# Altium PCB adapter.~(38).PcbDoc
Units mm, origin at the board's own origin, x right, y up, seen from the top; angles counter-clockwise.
Board outline 43.1 x 112 mm, 4 copper layers (Top Layer, Layer 1, Layer 2, Bottom Layer), stack 1.57 mm thick; 4 components, 39 nets, 158 pads, 97 vias.
Unrouted connection lines stored in the file: 79.
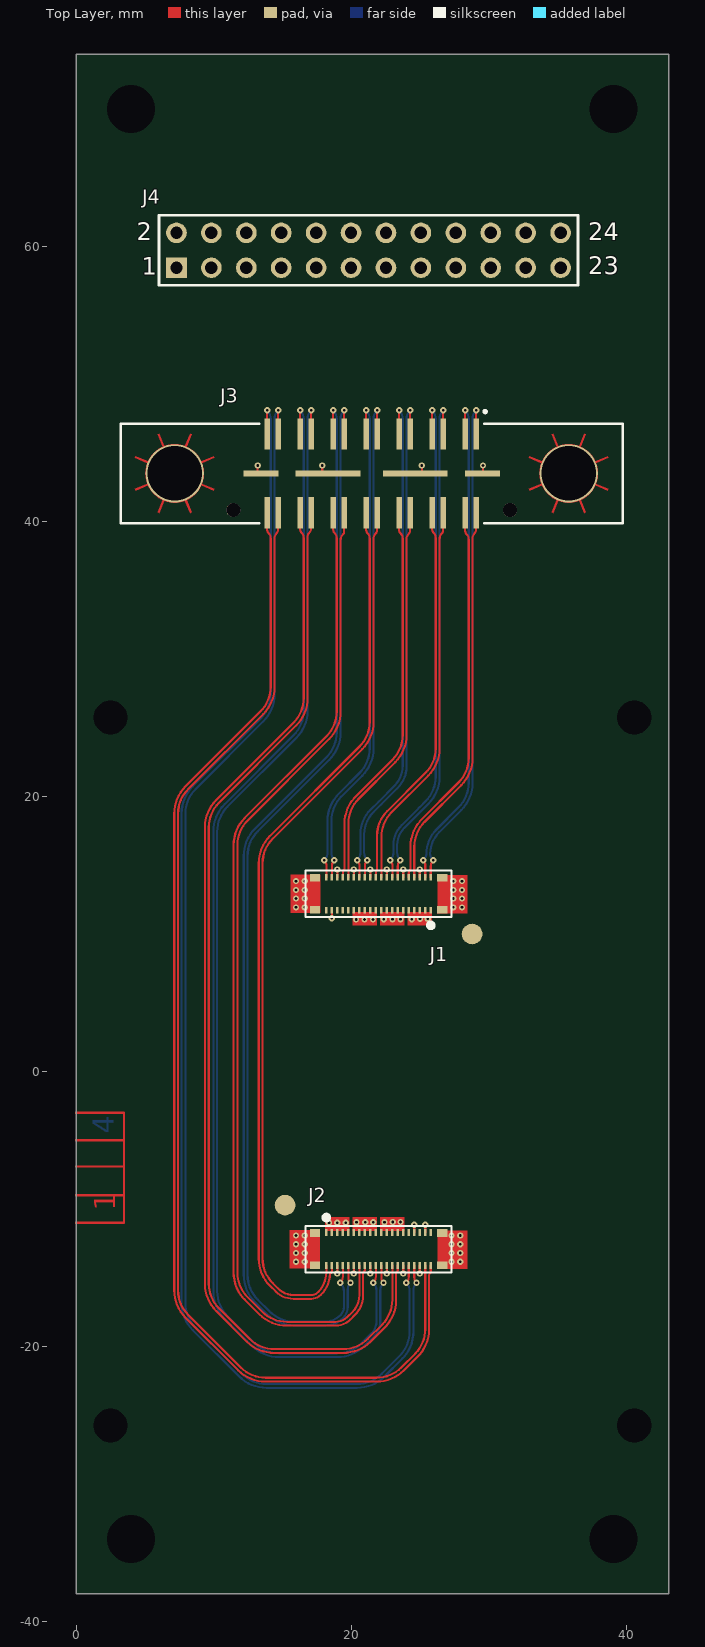
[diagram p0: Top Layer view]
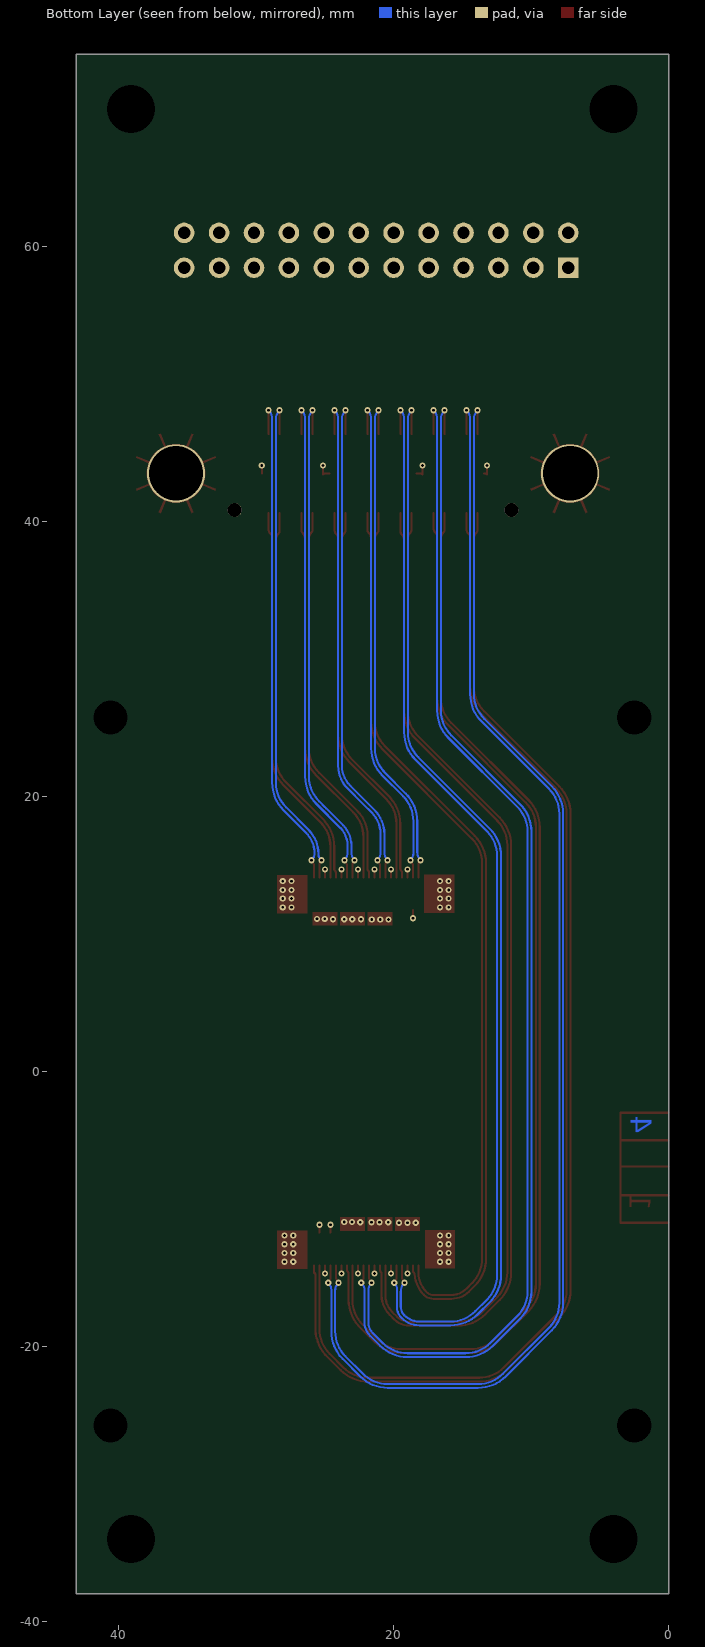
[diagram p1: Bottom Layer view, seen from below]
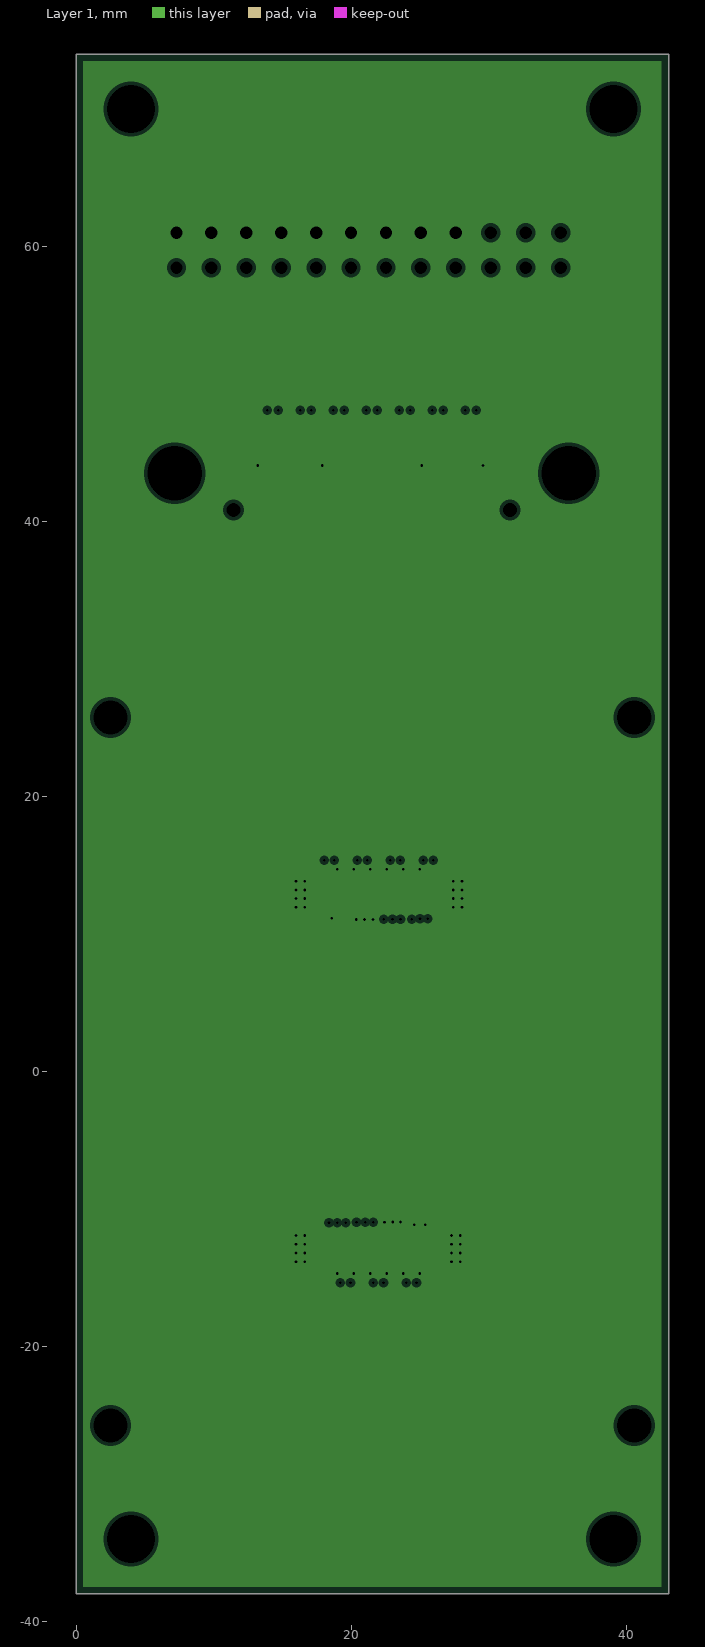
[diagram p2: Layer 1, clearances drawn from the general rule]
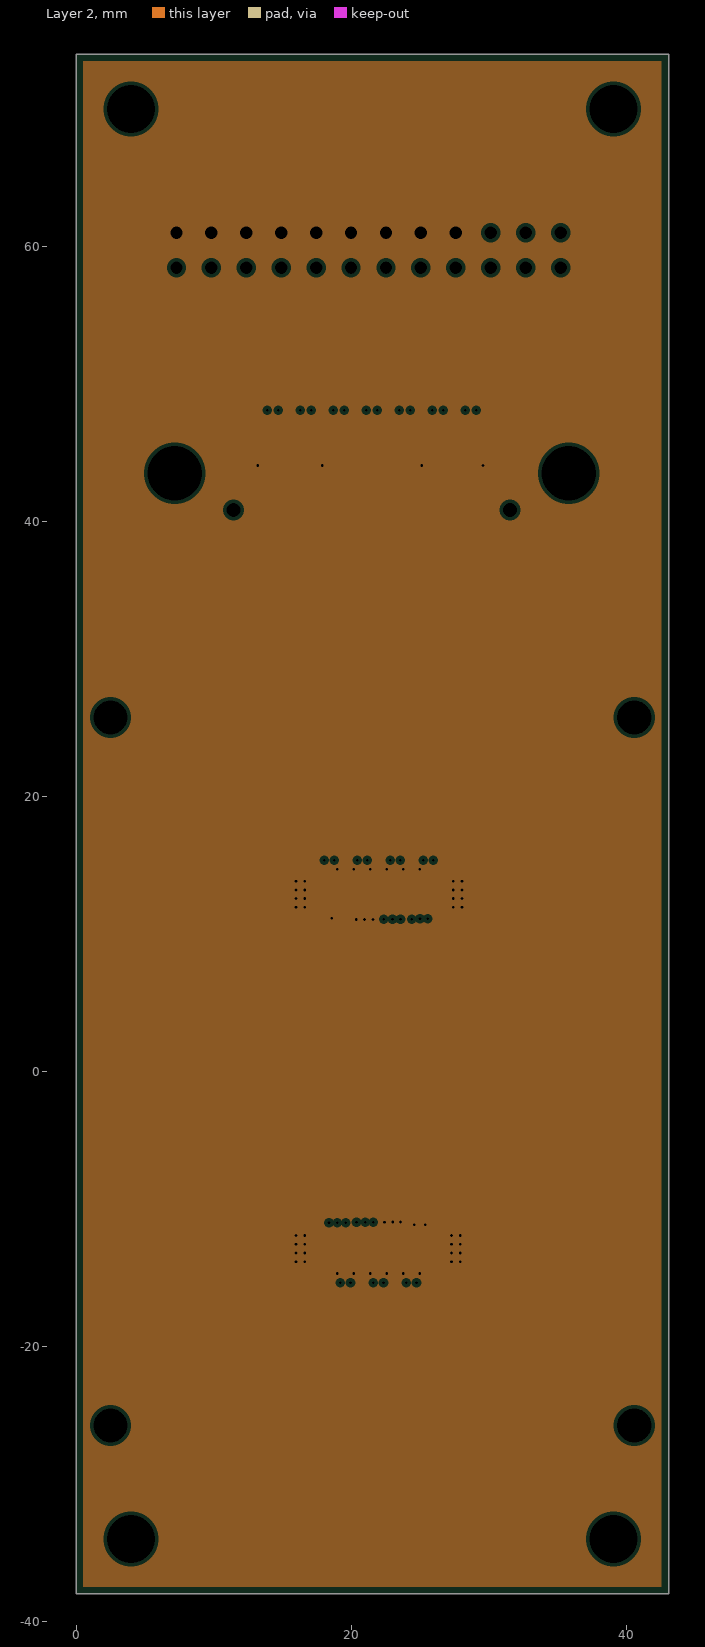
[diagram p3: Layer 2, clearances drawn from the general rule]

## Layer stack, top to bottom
Top Solder: solder mask 0.0102, Solder Resist, Dk 3.5
Top Layer: signal copper 0.035
Dielectric 1: prepreg 0.2, 7628, Dk 4.6
Layer 1: plane copper 0.0175, net GND
Dielectric 2: core 1.065, FR-4, Dk 4.5
Layer 2: plane copper 0.0175, net GND
Dielectric 3: prepreg 0.2, 7628, Dk 4.6
Bottom Layer: signal copper 0.035
Bottom Solder: solder mask 0.0102, Solder Resist, Dk 3.5

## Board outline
0,-38 43.1,-38 43.1,74 0,74

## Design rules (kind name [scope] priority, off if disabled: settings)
Clearance [All] p1: gap=0.2 ignorepadtopadclearanceinfootprint=FALSE except(0: Arc-Hole Track-Hole SMDPad-Hole THPad-Hole Via-Hole Fill-Hole Poly-Hole Region-Hole Text-Hole; 0.089: Arc-Via Track-Via SMDPad-Via Via-Via; 0.127: Arc-Arc Arc-Track Arc-THPad Track-Track Track-THPad THPad-Via; 0.15: Arc-SMDPad Track-SMDPad SMDPad-SMDPad; 0.254: Arc-Text Track-Text SMDPad-THPad SMDPad-Text THPad-THPad THPad-Text Via-Text Fill-Text Poly-Text Region-Text Text-Text)
DiffPairsRouting [All] p1: maxlimit=0.254 minlimit=0.127 mostfreqgap=0.127 toplayer_minwidth=0.152 toplayer_maxwidth=0.152 toplayer_prefwidth=0.152 bottomlayer_minwidth=0.152 bottomlayer_maxwidth=0.152 bottomlayer_prefwidth=0.152 maxuncoupledlength=12.7
HoleSize [All] p1: absolutevalues=TRUE maxlimit=5.08 minlimit=0.025 maxpercent=80.000 minpercent=20.000
MinimumSolderMaskSliver [All] p1: minsoldermaskwidth=0.12
PlaneClearance [All] p1: clearance=0.254
PlaneConnect [All] p1: pad.planeconnectstyle=Relief pad.reliefexpansion=0.508 pad.reliefentries=4 pad.reliefconductorwidth=0.254 pad.reliefairgap=0.254 via.planeconnectstyle=Direct via.reliefexpansion=0.508 via.reliefentries=4 via.reliefconductorwidth=0.254 via.reliefairgap=0.254
PolygonConnect [All] p1: connectstyle=Relief reliefconductorwidth=0.254 reliefentries=4 polygonreliefangle="90 Angle" airgapwidth=0.254
RoomDefinition emu_adapter [InComponentClass('emu_adapter')] p1: confinementstyle=ConfineIn formatcopy=TRUE lockcomponents=FALSE outline -2.8,-38 45.6,-38 45.6,74 -2.8,74
RoutingCorners [All] p1: cornerstyle=Round minsetback=2.54 maxsetback=2.54
RoutingVias [All] p1: holewidth=0.2 width=0.45 viastyle="Through Hole" minholewidth=0.2 minwidth=0.45 maxholewidth=0.3 maxwidth=0.55
SMDEntry [(InDifferentialPairClass('All Differential Pairs'))] p1: side=FALSE corner=FALSE anyangle=FALSE
SilkToSolderMaskClearance [IsPad] p1: minsilkscreentomaskgap=0.15 clearancetoexposedcopper=TRUE
SolderMaskExpansion [All] p1: expansion=0.038 istentingtop=FALSE
Width [All] p1: maxlimit=0.254 minlimit=0.152 preferedwidth=0.152 minimp=50.000000 maximp=50.000000 favimp=50.000000
23 further rules are at their usual default settings.

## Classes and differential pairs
differential pair T_EDIN3: +T_EDIN3_P -T_EDIN3_N
differential pair T_EDIN2: +T_EDIN2_P -T_EDIN2_N
differential pair T_EDIN1: +T_EDIN1_P -T_EDIN1_N
differential pair T_EDIN0: +T_EDIN0_P -T_EDIN0_N
differential pair EDOUT1: +EDOUT1_P -EDOUT1_N
differential pair EDOUT0: +EDOUT0_P -EDOUT0_N
differential pair EDIN3: +EDIN3_P -EDIN3_N
differential pair EDIN2: +EDIN2_P -EDIN2_N
differential pair EDIN1: +EDIN1_P -EDIN1_N
differential pair EDIN0: +EDIN0_P -EDIN0_N
differential pair ECLK3: +ECLK3_P -ECLK3_N
differential pair ECLK2: +ECLK2_P -ECLK2_N
differential pair ECLK1: +ECLK1_P -ECLK1_N
differential pair ECLK0: +ECLK0_P -ECLK0_N

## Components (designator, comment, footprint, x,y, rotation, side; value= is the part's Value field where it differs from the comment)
J1 "WP7B-S040VA1" WP7B-40R 25.8,11.725 r0 top locked
J2 "WP7B-S040VA1" WP7B-40R 18.2,-11.725 r180 top locked
J3 "QSE-014-01-X-D-DP-A-RT1" SAMTEC_QSE-014-01-X-D-DP-A-RT1 21.5,43.5 r180 top locked
J4 "Header 12X2" HDR2X12 7.3,58.46 r0 top

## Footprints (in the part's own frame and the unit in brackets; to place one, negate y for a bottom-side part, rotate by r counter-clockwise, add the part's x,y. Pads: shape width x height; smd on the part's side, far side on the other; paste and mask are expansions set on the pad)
HDR2X12 [mm] "Connector; Header; 12x2 Position"
  rect 1.5x1.5 hole 0.9: 1(0,0)
  round 1.5 hole 0.9: 2(0,2.54) 3(2.54,0) 4(2.54,2.54) 5(5.08,0) 6(5.08,2.54) 7(7.62,0) 8(7.62,2.54) 9(10.16,0) 10(10.16,2.54) 11(12.7,0) 12(12.7,2.54) 13(15.24,0) 14(15.24,2.54) 15(17.78,0) 16(17.78,2.54) 17(20.32,0) 18(20.32,2.54) 19(22.86,0) 20(22.86,2.54) 21(25.4,0) 22(25.4,2.54) 23(27.94,0) 24(27.94,2.54)
  silkscreen extent -1.27,-1.27 29.21,3.81
SAMTEC_QSE-014-01-X-D-DP-A-RT1 [mm]
  rect 0.41x2.27 smd: 01(-7.6,-2.865) 02(-7.6,2.865) 03(-6.8,-2.865) 04(-6.8,2.865) 05(-5.2,-2.865) 06(-5.2,2.865) 07(-4.4,-2.865) 08(-4.4,2.865) 09(-2.8,-2.865) 10(-2.8,2.865) 11(-2,-2.865) 12(-2,2.865) 13(-0.4,-2.865) 14(-0.4,2.865) 15(0.4,-2.865) 16(0.4,2.865) 17(2,-2.865) 18(2,2.865) 19(2.8,-2.865) 20(2.8,2.865) 21(4.4,-2.865) 22(4.4,2.865) 23(5.2,-2.865) 24(5.2,2.865) 25(6.8,-2.865) 26(6.8,2.865) 27(7.6,-2.865) 28(7.6,2.865)
  round 4.24 hole 3.96: 29(-14.33,0) 30(14.33,0)
  rect 2.54x0.43 smd: GND1(-8.065,0) GND4(8.065,0)
  rect 4.7x0.43 smd: GND2(-3.175,0) GND3(3.175,0)
  round 1.02 hole 1.02 unplated: ""(-10.065,2.67) ""(10.065,2.67)
  Top Layer region: 265 vertices and 0 holes, not listed, extent -17.219,-2.889 -11.442,2.889
  Top Layer region: 265 vertices and 0 holes, not listed, extent 11.442,-2.889 17.219,2.889
  silkscreen extent -18.26,-4.6 18.26,3.62
WP7B-40R [mm]
  rect 0.2x0.5 smd: 1(0,0) 2(-0.4,0) 3(-0.8,0) 4(-1.2,0) 5(-1.6,0) 6(-2,0) 7(-2.4,0) 8(-2.8,0) 9(-3.2,0) 10(-3.6,0) 11(-4,0) 12(-4.4,0) 13(-4.8,0) 14(-5.2,0) 15(-5.6,0) 16(-6,0) 17(-6.4,0) 18(-6.8,0) 19(-7.2,0) 20(-7.6,0) 21(-7.6,2.4) 22(-7.2,2.4) 23(-6.8,2.4) 24(-6.4,2.4) 25(-6,2.4) 26(-5.6,2.4) 27(-5.2,2.4) 28(-4.8,2.4) 29(-4.4,2.4) 30(-4,2.4) 31(-3.6,2.4) 32(-3.2,2.4) 33(-2.8,2.4) 34(-2.4,2.4) 35(-2,2.4) 36(-1.6,2.4) 37(-1.2,2.4) 38(-0.8,2.4) 39(-0.4,2.4) 40(0,2.4)
  rect 0.75x0.55 smd: 41(0.825,0.025) 42(-8.425,0.025) 43(-8.425,2.375) 44(0.825,2.375)
  silkscreen extent -9.1,-1.2 1.5,2.9, body extent -9.1,-0.05 1.5,2.45, height 0.5

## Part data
J1 J2: library part WP7B-40R, "receptacle"
J3: "28 Position Connector Differential Pair Array, Female Surface Mount Gold", Package=None
J4: "Header, 12-Pin, Dual row"

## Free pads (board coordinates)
  round 1 hole 2.5 unplated: 1(2.5,-25.75) 1(2.5,25.75) 1(40.6,-25.75) 1(40.6,25.75)
  round 1.5 smd paste-2: 1(28.8,10) 4(15.2,-9.725)
  round 1.5 hole 3.5: 5(39.1,70) 6(4,70) 7(39.1,-34) 8(4,-34)

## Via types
v1: diameter 0.45, hole 0.2, Top Layer to Bottom Layer, 97 vias

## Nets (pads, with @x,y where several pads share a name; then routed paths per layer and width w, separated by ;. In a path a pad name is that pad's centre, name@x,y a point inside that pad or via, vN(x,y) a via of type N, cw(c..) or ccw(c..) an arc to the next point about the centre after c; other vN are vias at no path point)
1V0A: J1.20 J4.23
1V2_mon0: J1.17 J4.19
1V2_mon1: J1.18 J4.21
1V2A: J1.1 J1.2 J1.3 J1.4 J1.5 J4.1 J4.3
  other v1: 24.409,11.074 25.019,11.1 25.578,11.1
1V2B: J1.6 J1.7 J1.8 J1.9 J1.10 J4.5 J4.7
  other v1: 22.377,11.074 23.012,11.074 23.597,11.074
1V2C: J2.1 J2.2 J2.3 J2.4 J2.5 J4.9 J4.11 J4.13
  other v1: 18.39,-10.998 18.999,-10.998 19.609,-10.998
1V2D: J2.6 J2.7 J2.8 J2.9 J2.10 J4.15 J4.17
  other v1: 20.396,-10.973 21.031,-10.973 21.615,-10.973
ECLK0_N: J1.39 J3.03 | length 37
  Top Layer w0.152: v1(25.247,15.367) cw(c24.878,14.998) 25.4,14.998 J1.39 ; J3.03 v1(28.3,48.099)
  Bottom Layer w0.152: v1(25.247,15.367) 25.315,15.435 ccw(c24.926,15.824) 25.476,15.824 ; 25.476,15.825 cw(c27.989,15.825) 26.212,17.601 27.816,19.206 ccw(c26.02,21.002) 28.56,21.002 28.56,47.471 ccw(c27.672,47.471) v1(28.3,48.099)
ECLK0_P: J1.40 J3.01 | length 37
  Top Layer w0.152: J1.40 25.8,14.924 cw(c26.427,14.924) v1(25.984,15.367) ; v1(29.1,48.099) J3.01 J3.01
  Bottom Layer w0.152: v1(25.984,15.367) 25.918,15.433 cw(c26.309,15.824) 25.756,15.824 cw(c27.99,15.824) 26.41,17.404 28.015,19.009 ccw(c26.023,21.001) 28.84,21.001 ; 28.84,21.001 28.84,47.471 cw(c29.728,47.471) v1(29.1,48.099)
ECLK1_N: J1.28 J3.09 | length 37
  Top Layer w0.152: J1.28 21,14.924 cw(c21.627,14.924) v1(21.184,15.367) ; v1(24.299,48.1) J3.09 J3.09
  Bottom Layer w0.152: v1(21.184,15.367) cw(c21.735,15.919) 20.955,15.919 20.955,17.252 cw(c23.21,17.252) 21.615,18.847 22.2,19.431 23.36,20.592 ccw(c21.722,22.23) 24.039,22.23 24.039,47.472 cw(c24.928,47.472) v1(24.299,48.1)
ECLK1_P: J1.27 J3.11 | length 37
  Top Layer w0.152: v1(20.447,15.367) cw(c20.078,14.998) 20.6,14.998 J1.27 ; J3.11 v1(23.499,48.1)
  Bottom Layer w0.152: v1(20.447,15.367) ccw(c19.895,15.919) 20.676,15.919 20.676,17.252 cw(c23.21,17.252) 21.418,19.044 22.002,19.629 23.16,20.786 ccw(c21.712,22.234) 23.76,22.234 23.76,47.472 ccw(c22.871,47.472) v1(23.499,48.1)
ECLK2_N: J2.40 J3.14 | length 65.1
  Top Layer w0.152: J2.40 18.2,-14.61 cw(c16.159,-14.61) 17.602,-16.053 cw(c17.112,-15.562) 17.112,-16.256 15.81,-16.256 cw(c15.81,-14.695) 14.707,-15.799 14.308,-15.4 cw(c16.104,-13.604) 13.564,-13.604 13.564,15.139 cw(c16.104,15.139) 14.308,16.935 20.815,23.442 ccw(c18.823,25.434) 21.64,25.434 21.64,38.771 cw(c22.164,38.771) 21.793,39.141 ccw(c21.535,39.399) 21.9,39.399 J3.14
ECLK2_P: J2.39 J3.16 | length 66.1
  Top Layer w0.152: 17.799,-16.251 cw(c17.113,-15.565) 17.113,-16.535 15.807,-16.535 cw(c15.807,-14.702) 14.511,-15.999 14.109,-15.596 cw(c16.101,-13.605) 13.284,-13.605 13.284,15.14 cw(c16.101,15.14) 14.109,17.132 20.616,23.639 ccw(c18.82,25.435) 21.36,25.435 21.36,38.776 ccw(c20.844,38.776) 21.209,39.141 cw(c21.472,39.405) 21.1,39.405 J3.16 ; 17.801,-16.249 ccw(c16.159,-14.61) 18.204,-15.707 ccw(c16.159,-14.61) 18.477,-14.705 cw(c19.487,-15.525) 18.567,-14.605 ccw(c18.489,-14.526) 18.6,-14.526 J2.39
ECLK3_N: J2.28 J3.22 | length 79
  Top Layer w0.152: J3.22 17.099,39.511 cw(c16.648,39.511) 16.967,39.192 ccw(c17.276,38.883) 16.839,38.883 16.839,27.161 cw(c14.022,27.161) 16.014,25.169 10.396,19.551 ccw(c12.192,17.755) 9.652,17.755 9.652,-15.432 ccw(c12.192,-15.432) 10.396,-17.229 12.616,-19.449 ccw(c14.413,-17.653) 14.413,-20.193 19.42,-20.193 ccw(c19.42,-17.653) 21.216,-19.449 22.256,-18.409 ccw(c20.46,-16.613) 23,-16.613 J2.28
ECLK3_P: J2.27 J3.24 | length 79.9
  Top Layer w0.152: J3.24 16.299,39.43 ccw(c16.672,39.43) 16.408,39.167 cw(c16.043,38.802) 16.56,38.802 16.56,27.162 cw(c14.02,27.162) 15.816,25.366 10.198,19.748 ccw(c12.19,17.756) 9.373,17.756 9.373,-15.434 ccw(c12.189,-15.434) 10.198,-17.425 12.419,-19.647 ccw(c14.412,-17.655) 14.412,-20.472 19.421,-20.472 ccw(c19.421,-17.655) 21.413,-19.647 22.574,-18.486 22.574,-18.479 ccw(c20.46,-16.613) 23.279,-16.613 23.279,-14.647 cw(c23.736,-14.897) 23.368,-14.529 ccw(c23.291,-14.452) 23.4,-14.452 J2.27
EDIN0_N: J1.34 J3.05 | length 37
  Top Layer w0.152: J1.34 23.4,14.924 cw(c24.027,14.924) v1(23.584,15.367) ; v1(26.7,48.1) J3.05 J3.05
  Bottom Layer w0.152: v1(23.584,15.367) cw(c24.135,15.919) 23.355,15.919 23.355,16.459 cw(c25.129,16.459) 23.875,17.714 25.614,19.453 ccw(c23.622,21.445) 26.439,21.445 26.439,47.472 cw(c27.328,47.472) v1(26.7,48.1)
EDIN0_P: J1.33 J3.07 | length 36.8
  Top Layer w0.152: v1(22.847,15.367) cw(c22.478,14.998) 23,14.998 J1.33 ; J3.07 v1(25.9,48.1)
  Bottom Layer w0.152: v1(22.847,15.367) ccw(c22.295,15.919) 23.076,15.919 23.076,16.46 cw(c25.127,16.46) 23.677,17.911 24.912,19.146 ; 24.994,19.228 25.416,19.65 ccw(c23.62,21.446) 26.16,21.446 26.16,47.472 ccw(c25.271,47.472) v1(25.9,48.1)
EDIN1_N: J1.25 J3.10 | length 28.1
  Top Layer w0.152: J1.25 19.8,18.023 cw(c22.34,18.023) 20.544,19.819 23.215,22.49 ccw(c21.223,24.482) 24.04,24.482 24.04,38.751 cw(c24.521,38.751) 24.181,39.091 ccw(c23.892,39.379) 24.3,39.379 J3.10
EDIN1_P: J1.24 J3.12 | length 28.1
  Top Layer w0.152: J1.24 19.4,14.458 cw(c19.679,14.458) 19.482,14.656 ccw(c19.388,14.749) 19.521,14.749 19.521,18.023 cw(c22.34,18.023) 20.226,19.888 20.226,19.896 23.017,22.686 ccw(c21.221,24.483) 23.761,24.483 23.761,38.745 ccw(c23.201,38.745) 23.597,39.141 cw(c23.829,39.374) 23.5,39.374 J3.12
EDIN2_N: J2.34 J3.18 | length 72.2
  Top Layer w0.152: J3.18 19.5,39.257 cw(c19.265,39.257) 19.431,39.091 ccw(c19.894,38.628) 19.239,38.628 19.239,26.183 cw(c16.422,26.183) 18.414,24.191 12.479,18.256 ccw(c14.275,16.46) 11.735,16.46 11.735,-14.62 ccw(c14.275,-14.62) 12.479,-16.416 13.531,-17.468 ccw(c15.327,-15.672) 15.327,-18.212 18.872,-18.212 ccw(c18.872,-16.985) 19.739,-17.853 20.091,-17.501 ccw(c18.864,-16.273) 20.6,-16.273 J2.34
EDIN2_P: J2.33 J3.20 | length 73.1
  Top Layer w0.152: J3.20 18.7,39.435 ccw(c19.115,39.435) 18.821,39.141 cw(c18.487,38.807) 18.96,38.807 18.96,26.184 cw(c16.42,26.184) 18.216,24.388 12.281,18.453 ccw(c14.273,16.461) 11.455,16.461 11.455,-14.621 ccw(c14.272,-14.621) 12.28,-16.612 13.334,-17.666 ccw(c15.326,-15.674) 15.326,-18.491 18.873,-18.491 ccw(c18.873,-16.988) 19.936,-18.051 20.29,-17.697 ccw(c18.867,-16.274) 20.879,-16.274 20.879,-14.668 cw(c21.2,-14.799) 20.955,-14.554 ccw(c20.846,-14.446) 21,-14.446 J2.33
EDIN3_N: J2.25 J3.25 | length 95.2
  Top Layer w0.152: v1(14.698,48.1) J3.25 J3.25 ; v1(24.016,-15.367) ccw(c23.573,-14.924) 24.2,-14.924 J2.25
  Bottom Layer w0.152: v1(14.698,48.1) ccw(c15.327,47.472) 14.438,47.472 14.438,27.452 cw(c11.621,27.452) 13.613,25.46 8.694,20.542 ccw(c10.49,18.746) 7.95,18.746 7.95,-16.829 ccw(c10.49,-16.829) 8.694,-18.626 12.058,-21.989 ccw(c13.854,-20.193) 13.854,-22.733 20.436,-22.733 ccw(c20.436,-20.193) 22.232,-21.989 23.513,-20.708 ccw(c21.717,-18.912) 24.257,-18.912 24.257,-15.948 ccw(c23.436,-15.948) v1(24.016,-15.367)
EDIN3_P: J2.24 J3.27 | length 96.1
  Top Layer w0.152: J3.27 v1(13.898,48.1) ; J2.24 24.6,-14.998 ccw(c25.122,-14.998) v1(24.753,-15.367)
  Bottom Layer w0.152: v1(13.898,48.1) cw(c13.27,47.472) 14.159,47.472 14.159,27.453 cw(c11.619,27.453) 13.415,25.657 8.496,20.739 ccw(c10.488,18.747) 7.671,18.747 7.671,-16.831 ccw(c10.487,-16.831) 8.496,-18.822 11.861,-22.187 ccw(c13.853,-20.195) 13.853,-23.012 20.437,-23.012 ccw(c20.437,-20.195) 22.429,-22.187 23.711,-20.905 ccw(c21.719,-18.913) 24.536,-18.913 24.536,-15.89 cw(c25.276,-15.89) v1(24.753,-15.367)
EDOUT0_N: J1.37 J3.02 | length 28.1
  Top Layer w0.152: J1.37 24.6,16.353 cw(c27.14,16.353) 25.344,18.149 28.015,20.82 ccw(c26.024,22.812) 28.841,22.812 28.841,38.801 cw(c29.321,38.801) 28.981,39.141 ccw(c28.693,39.43) 29.101,39.43 J3.02
EDOUT0_P: J1.36 J3.04 | length 28.1
  Top Layer w0.152: J1.36 24.2,14.431 cw(c24.481,14.431) 24.282,14.63 ccw(c24.19,14.723) 24.321,14.723 24.321,16.353 cw(c27.14,16.353) 25.026,18.218 25.026,18.226 27.817,21.017 ccw(c26.021,22.813) 28.561,22.813 28.561,38.695 ccw(c28.001,38.695) 28.397,39.091 cw(c28.63,39.323) 28.301,39.323 J3.04
EDOUT1_N: J2.37 J3.17 | length 79.7
  Top Layer w0.152: v1(19.216,-15.367) ccw(c18.773,-14.924) 19.4,-14.924 J2.37 ; v1(19.499,48.1) J3.17 J3.17
  Bottom Layer w0.152: v1(19.216,-15.367) cw(c18.576,-16.008) 19.482,-16.008 19.482,-17.116 cw(c18.615,-17.116) 19.228,-17.729 cw(c18.124,-16.625) 18.124,-18.186 15.86,-18.186 cw(c15.86,-15.646) 14.064,-17.442 13.215,-16.594 cw(c15.011,-14.797) 12.471,-14.797 12.471,15.672 cw(c15.011,15.672) 13.215,17.468 18.413,22.666 ccw(c16.421,24.658) 19.238,24.658 19.239,47.472 cw(c20.127,47.472) v1(19.499,48.1)
EDOUT1_P: J2.36 J3.19 | length 80.6
  Top Layer w0.152: J3.19 v1(18.699,48.1) ; J2.36 19.8,-14.998 ccw(c20.322,-14.998) v1(19.953,-15.367)
  Bottom Layer w0.152: v1(18.699,48.1) cw(c18.07,47.472) 18.959,47.472 18.959,24.659 cw(c16.419,24.659) 18.215,22.863 13.017,17.665 ccw(c15.009,15.673) 12.192,15.673 12.192,-14.799 ccw(c15.009,-14.799) 13.017,-16.79 13.867,-17.641 ccw(c15.86,-15.648) 15.86,-18.466 18.126,-18.466 ccw(c18.126,-16.631) 19.424,-17.928 19.427,-17.925 ccw(c18.62,-17.118) 19.761,-17.118 19.761,-15.83 cw(c20.416,-15.83) v1(19.953,-15.367)
GND: J1.11 J1.12 J1.13 J1.14 J1.15 J1.19 J1.23 J1.26 J1.29 J1.32 J1.35 J1.38 J1.41 J1.42 J1.43 J1.44 J2.11 J2.12 J2.13 J2.14 J2.15 J2.17 J2.19 J2.23 J2.26 J2.29 J2.32 J2.35 J2.38 J2.41 J2.42 J2.43 J2.44 J3.GND1 J3.GND2 J3.GND3 J3.GND4 J4.2 J4.4 J4.6 J4.8 J4.10 J4.12 J4.14 J4.16 J4.18 | length 12.3
  Top Layer w0.152: v1(13.208,44.069) 13.208,43.434 cw(c13.367,43.275) 13.367,43.5 J3.GND4@13.436,43.5 ; v1(17.907,44.069) 17.907,43.434 cw(c18.066,43.275) 18.066,43.5 J3.GND3 ; v1(18.6,11.15) J1.19 ; v1(19,-14.7) J2.38 ; J1.23 v1(19,14.7) ; v1(20.2,-14.7) J2.35 ; J1.26 v1(20.2,14.7) ; v1(21.4,-14.7) J2.32 ; J1.29 v1(21.4,14.7) ; v1(22.6,-14.7) J2.29 ; J1.32 v1(22.6,14.7) ; v1(23.8,-14.7) J2.26 ; J1.35 v1(23.8,14.7) ; J2.17 v1(24.6,-11.15) ; J3.GND2 24.987,43.5 cw(c24.987,43.275) 25.146,43.434 v1(25.146,44.069) ; v1(25,-14.7) J2.23 ; J1.38 v1(25,14.7) ; J2.19 v1(25.4,-11.15) ; J3.GND1 ccw(c29.501,43.564) 29.591,43.564 v1(29.591,44.069)
  other v1: 16.002,-13.843 16.637,-13.843 27.305,-13.843 27.94,-13.843 16.002,-13.208 16.637,-13.208 27.305,-13.208 27.94,-13.208 16.002,-12.573 16.637,-12.573 27.305,-12.573 27.94,-12.573 16.002,-11.938 16.637,-11.938 27.305,-11.938 27.94,-11.938 22.428,-10.973 23.038,-10.947 23.597,-10.947 20.371,11.049 20.98,11.049 21.59,11.049 16.002,11.938 16.637,11.938 27.432,11.938 28.067,11.938 16.002,12.573 16.637,12.573 27.432,12.573 28.067,12.573 16.002,13.208 16.637,13.208 27.432,13.208 28.067,13.208 16.002,13.843 16.637,13.843 27.432,13.843 28.067,13.843
RSTB: J1.16 J4.24
SCL: J2.20 J4.20
SDA: J2.18 J4.22
T_EDIN0_N: J1.31 J3.06 | length 28.1
  Top Layer w0.152: J1.31 22.2,17.053 cw(c24.74,17.053) 22.944,18.849 25.615,21.52 ccw(c23.623,23.512) 26.44,23.512 26.44,38.699 cw(c27.138,38.699) 26.645,39.192 ccw(c26.509,39.328) 26.701,39.328 J3.06
T_EDIN0_P: J1.30 J3.08 | length 28.2
  Top Layer w0.152: J1.30 21.8,14.463 cw(c22.037,14.463) 21.869,14.63 ccw(c21.808,14.692) 21.895,14.692 21.895,17.161 cw(c24.391,17.161) 22.626,18.926 25.417,21.717 ccw(c23.621,23.513) 26.161,23.513 26.161,38.802 ccw(c25.644,38.802) 26.01,39.167 cw(c26.273,39.43) 25.901,39.43 J3.08
T_EDIN1_N: J1.22 J3.13 | length 36.9
  Top Layer w0.152: J1.22 18.6,14.924 cw(c19.227,14.924) v1(18.784,15.367) ; v1(21.899,48.1) J3.13 J3.13
  Bottom Layer w0.152: v1(18.784,15.367) cw(c19.306,15.889) 18.567,15.889 18.567,18.212 cw(c21.107,18.212) 19.311,20.008 20.814,21.511 ccw(c18.822,23.503) 21.639,23.503 21.639,47.472 cw(c22.528,47.472) v1(21.899,48.1)
T_EDIN1_P: J1.21 J3.15 | length 36.9
  Top Layer w0.152: v1(18.047,15.367) cw(c17.678,14.998) 18.2,14.998 J1.21 ; J3.15 v1(21.099,48.1)
  Bottom Layer w0.152: v1(18.047,15.367) ccw(c17.465,15.949) 18.288,15.949 18.288,18.213 cw(c21.105,18.213) 19.113,20.205 20.615,21.708 ccw(c18.819,23.504) 21.359,23.504 21.359,47.472 ccw(c20.471,47.472) v1(21.099,48.1)
T_EDIN2_N: J2.31 J3.21 | length 87.5
  Top Layer w0.152: v1(17.099,48.1) J3.21 J3.21 ; v1(21.616,-15.367) ccw(c21.173,-14.924) 21.8,-14.924 J2.31
  Bottom Layer w0.152: v1(17.099,48.1) ccw(c17.727,47.472) 16.838,47.472 16.838,26.246 cw(c14.021,26.246) 16.013,24.254 11.006,19.246 ccw(c12.802,17.45) 10.262,17.45 10.262,-15.991 ccw(c12.802,-15.991) 11.006,-17.787 12.972,-19.754 ccw(c14.768,-17.958) 14.768,-20.498 18.988,-20.498 ccw(c18.988,-17.958) 20.785,-19.754 21.514,-19.025 ccw(c20.717,-18.227) 21.844,-18.227 21.844,-15.916 ccw(c21.067,-15.916) v1(21.616,-15.367)
T_EDIN2_P: J2.30 J3.23 | length 88.4
  Top Layer w0.152: J3.23 v1(16.299,48.1) ; J2.30 22.2,-14.998 ccw(c22.722,-14.998) v1(22.353,-15.367)
  Bottom Layer w0.152: v1(16.299,48.1) cw(c15.67,47.472) 16.559,47.472 16.559,26.247 cw(c14.019,26.247) 15.815,24.451 10.807,19.443 ccw(c12.799,17.451) 9.982,17.451 9.982,-15.992 ccw(c12.799,-15.992) 10.807,-17.984 12.775,-19.952 ccw(c14.767,-17.96) 14.767,-20.777 18.989,-20.777 ccw(c18.989,-17.96) 20.981,-19.952 21.712,-19.222 ccw(c20.718,-18.228) 22.123,-18.228 22.123,-15.921 cw(c22.907,-15.921) v1(22.353,-15.367)
T_EDIN3_N: J2.22 J3.26 | length 86.8
  Top Layer w0.152: J3.26 14.699,39.43 cw(c14.291,39.43) 14.58,39.141 ccw(c14.92,38.801) 14.439,38.801 14.439,27.987 cw(c11.622,27.987) 13.614,25.995 8.161,20.542 ccw(c9.957,18.746) 7.417,18.746 7.417,-15.915 ccw(c9.957,-15.915) 8.161,-17.711 11.981,-21.532 ccw(c13.778,-19.736) 13.778,-22.276 21.859,-22.276 ccw(c21.859,-19.736) 23.655,-21.532 24.656,-20.531 ccw(c22.86,-18.734) 25.4,-18.734 J2.22
T_EDIN3_P: J2.21 J3.28 | length 87.7
  Top Layer w0.152: J3.28 13.899,39.399 ccw(c14.228,39.399) 13.995,39.167 cw(c13.599,38.771) 14.159,38.771 14.159,27.988 cw(c11.619,27.988) 13.415,26.192 7.963,20.739 ccw(c9.955,18.747) 7.137,18.747 7.137,-15.916 ccw(c9.954,-15.916) 7.962,-17.908 11.784,-21.73 ccw(c13.777,-19.738) 13.777,-22.555 21.86,-22.555 ccw(c21.86,-19.738) 23.852,-21.73 24.974,-20.608 cw(c25.317,-20.608) 24.974,-20.6 ccw(c22.86,-18.734) 25.31,-20.13 ccw(c22.86,-18.734) 25.593,-19.428 ccw(c24.032,-18.901) 25.679,-18.901 25.679,-14.791 cw(c26.088,-14.937) 25.781,-14.63 ccw(c25.735,-14.585) 25.8,-14.585 J2.21
pads on no net: J2.16 J3. J3.29 J3.30
copper on no net: | length 25.5
  Top Layer w0.152: 0,-9 3.5,-9 ; 0,-6.9 3.5,-6.9 ; 0,-5 3.5,-5 ; 0,-3 3.5,-3 3.5,-5 ; 0.014,-11 3.5,-11 3.5,-9 ; 3.5,-9 3.5,-6.9 ; 3.5,-6.9 3.5,-5

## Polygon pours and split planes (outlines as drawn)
GND on Layer 1 (split plane): 42.59,-37.49 0.51,-37.49 0.51,73.49 42.59,73.49
GND on Layer 2 (split plane): 42.59,-37.49 0.51,-37.49 0.51,73.49 42.59,73.49

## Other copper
Top Layer:
  region net GND: 23.9,-10.6 22.1,-10.6 22.1,-11.6 23.9,-11.6
  region net 1V2D: 21.9,-10.6 20.1,-10.6 20.1,-11.6 21.9,-11.6
  region net 1V2C: 19.9,-10.6 18.1,-10.6 18.1,-11.6 19.9,-11.6
  rectangle net 1V2A: 24.1,10.6 25.9,11.6
  rectangle net 1V2B: 22.1,10.6 23.9,11.6
  rectangle net GND: 20.1,10.6 21.9,11.6
  rectangle net GND: 26.273,-14.352 28.473,-11.552
  rectangle net GND: 15.535,-14.325 17.735,-11.525
  rectangle net GND: 15.592,11.525 17.792,14.325
  rectangle net GND: 26.273,11.498 28.473,14.298
  text "1" at 2.846,-10.146 h1.52 r90
  text "'.Pcb_File_Name_No_Path'" at 0.854,-62.438 h1.52
  text "'.Print_Date'" at 29.054,-63.046 h1.52
  text "'.Layer_Name'" at 0.854,-65.238 h1.52
Bottom Layer:
  text "4" at 2.746,-4.546 h1.52 r90
  text "'.Pcb_File_Name_No_Path'" at 0.923,-62.705 h1.52
  text "'.Print_Date'" at 29.123,-63.313 h1.52
  text "'.Layer_Name'" at 0.923,-65.505 h1.52

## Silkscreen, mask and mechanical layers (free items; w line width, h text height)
Mechanical 1:
  the board outline again, w0.102
Mechanical 14 (Mech14):
  text "'.Pcb_File_Name_No_Path'" at 1.123,-62.605 h1.52
  text "'.Print_Date'" at 29.323,-63.213 h1.52
  text "'.Layer_Name'" at 1.123,-65.913 h1.52

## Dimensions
0,60 to 0,-60 on Mechanical 14 (Mech14)
0,60 to 43.1,60 on Mechanical 14 (Mech14)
